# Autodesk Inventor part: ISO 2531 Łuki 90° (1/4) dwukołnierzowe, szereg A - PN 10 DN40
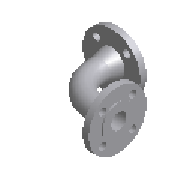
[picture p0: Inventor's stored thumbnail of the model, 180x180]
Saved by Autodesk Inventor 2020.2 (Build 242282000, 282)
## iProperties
Manager: www.cadconsulting.pl
Company: Fabian Stasiak CAD Consulting
NAME: PIPING: ISO 2531 90 Deg Double Flanged Bend - PN 10
DATA: <meta><inlinegroups number="0" deflen="0"></inlinegroups><connections number="2"></connections><angles><a>1.5707963267949</a></angles></meta>
IsCustomPart: 0
Created: 2014-02
Part Number: ISO 2531 Łuki 90° (1/4) dwukołnierzowe, szereg A - PN 10 DN40
Material: Żeliwo sferoidalne
Description: Rury, łączniki, akcesoria z żeliwa sferoidalnego i ich złącza do zastosowań w instalacjach wodnych lub gazowych - Łuki 90° (1/4) dwukołnierzowe - PN 10
Document SubType Name: Modeling
Standard: ISO 2531
Designer: F.Stasiak
Standard Revision: Fifth edition 1998-08-15
Standards Organization: ISO
Language: pl-PL
Size Designation: DN40
Categories: <MemberInstance><Categories><Category DisplayName="Rury cienko- i grubościenne" InternalName="4347fa0f-2144-441d-94cd-e3e15c92b736" Mnemonic="TUBEANDPIPE"><Cate
Density: 7.15 g/cm^3
Appearance: Ciemnoszary
Catalog Web Link: www.expertbooks.pl
Author: F.Stasiak
Subject: Zbiór ćwiczeń. Autodesk Inventor 2020. Kurs Professional
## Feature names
1. Revolution1
2. Sweep1
3. Revolution2
4. Extrusion1
5. Circular Pattern1
6. Extrusion2
7. Circular Pattern2
## Parameters: L2 = 19 mm, f1 = 3 mm, d11 = 84 mm, e = 7 mm, C7 = 19 mm, d2 = 7 mm, d3 = 84 mm, d4 = 3 mm, d5 = 15 deg, d15 = 90 deg, d9 = 7 mm, d10 = 3 mm, d13 = 84 mm, d18 = 7 mm, d19 = 0, d27 = 90 deg, d21 = 16 mm, d22 = 0, d24 = 360 deg, d26 = 16 mm, d28 = 0, d30 = 360 deg, d31 = 19 mm, d32 = 19 mm, d34 = 19 mm, d35 = 45 deg, d36 = 45 deg, d37 = 19 mm, d48 = 0, Size_Designation = 12.345 mm
